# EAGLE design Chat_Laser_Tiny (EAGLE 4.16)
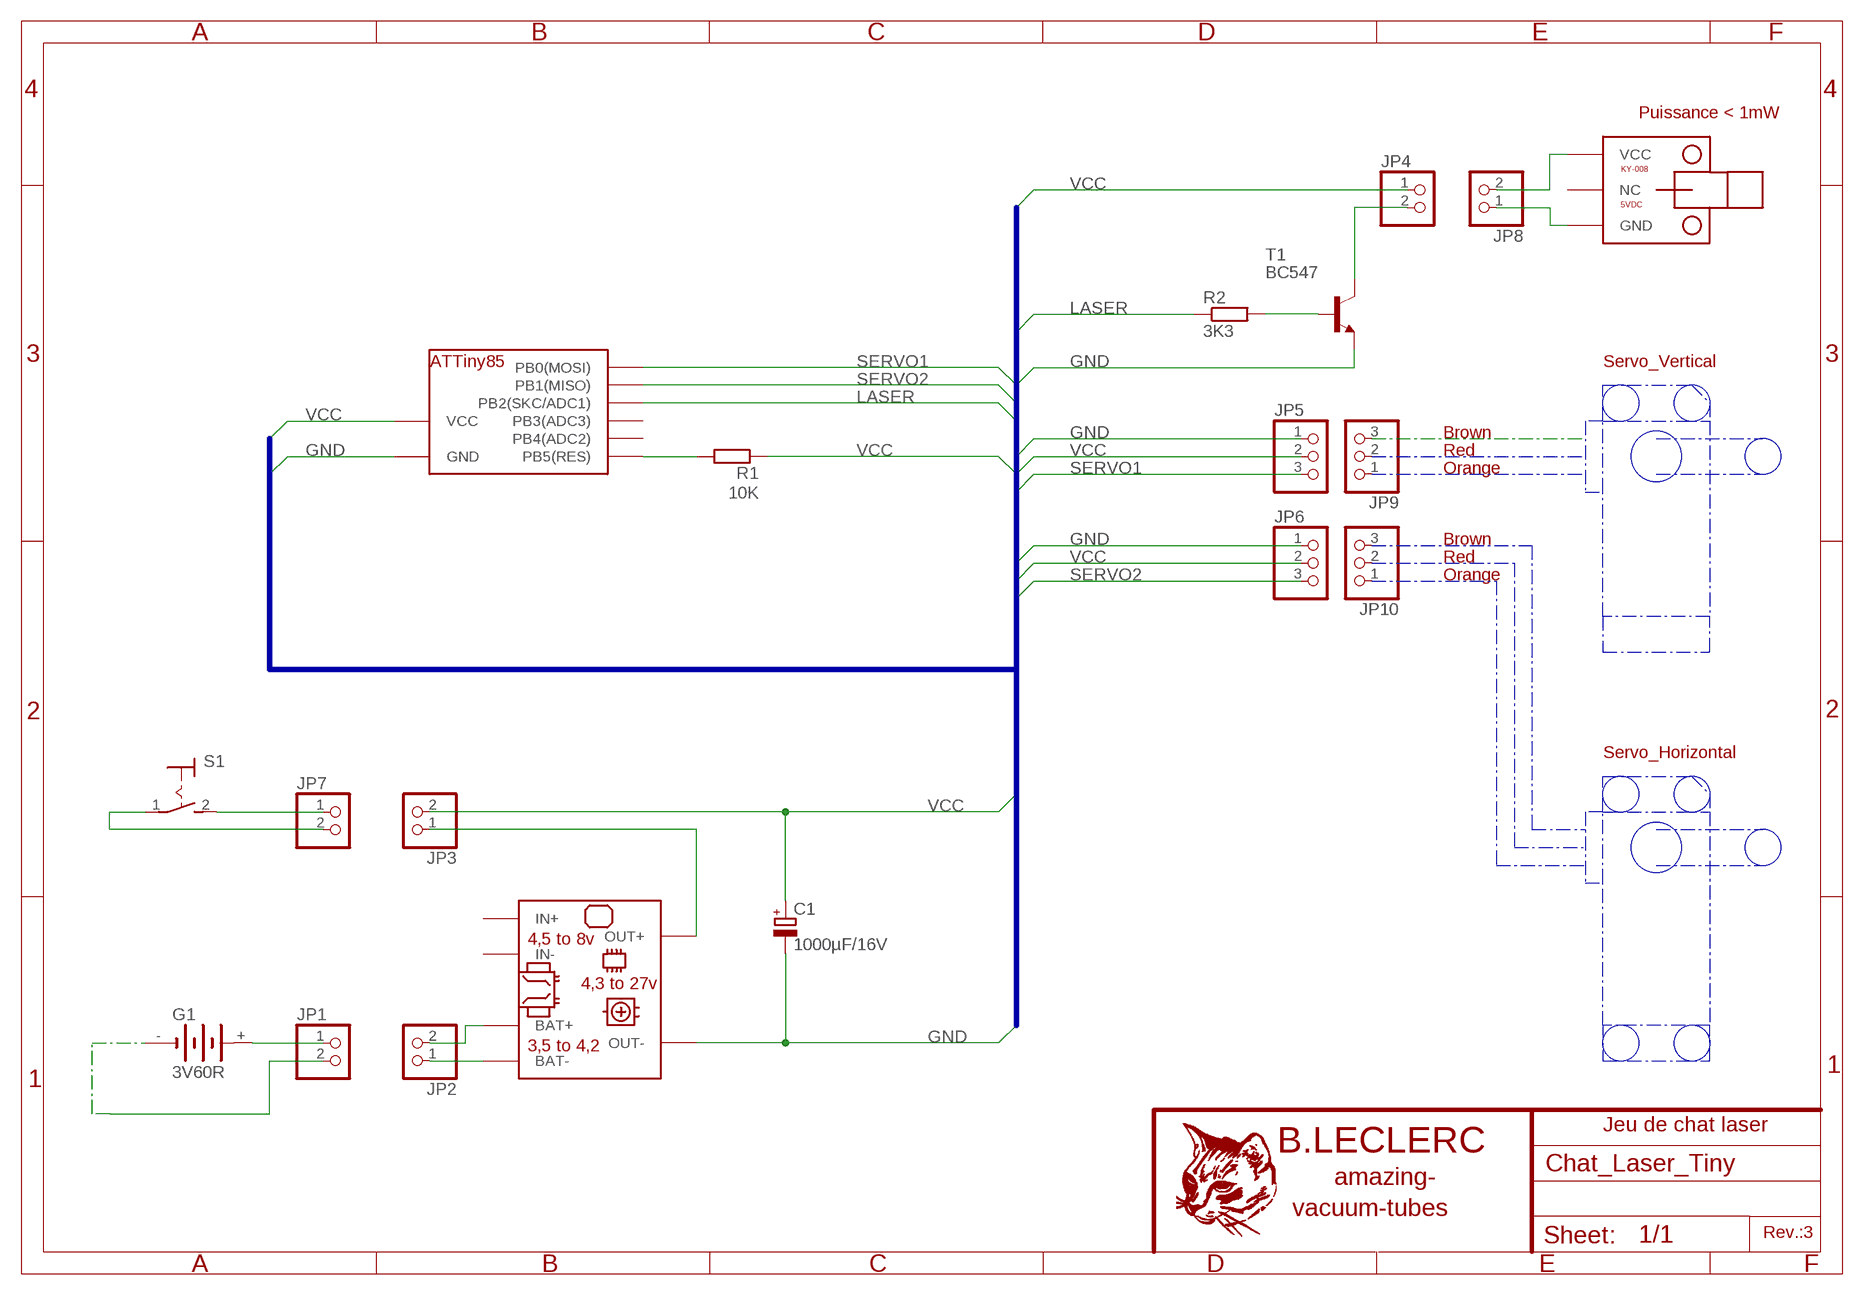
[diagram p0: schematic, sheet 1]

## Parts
C1  1000µF/16V  CPOL-EUE5-8.5  [E5-8,5]
G1  3V60R  [3V60R]
JP1  PINHD-1X2  [1X02]
JP2  PINHD-1X2  [1X02]
JP3  PINHD-1X2  [1X02]
JP4  PINHD-1X2  [1X02]
JP5  PINHD-1X3  [1X03]
JP6  PINHD-1X3  [1X03]
JP7  PINHD-1X2  [1X02]
JP8  PINHD-1X2  [1X02]
JP9  PINHD-1X3  [1X03]
JP10  PINHD-1X3  [1X03]
R1  10K  R-EU_M1206  [M1206]
R2  3K3  R-EU_M1206  [M1206]
S1  MS243  [MS243]
T1  BC547  [TO92]
U$2  LITHIUM_BAT_BOOST  [LITHIUM_BAT_BOOST]
U$3  KY-008_LASER  [KY-008_LASER]
U$4  ATTINY85  [DIL08]

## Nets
GND: C1.- JP5.1 JP6.1 T1.1(E) U$2.OUT- U$4.4(GND)
LASER: R2.1 U$4.7(PB2(SKC/ADC1))
N$1: R1.2 U$4.1(PB5(RES))
N$2: JP4.2 T1.3(C)
N$3: R2.2 T1.2(B)
N$6: G1.+ JP1.1
N$7: G1.- JP1.2
N$8: JP2.1 U$2.BAT-
N$9: JP2.2 U$2.BAT+
N$10: JP3.1 U$2.OUT+
N$11: JP7.2 S1.1(P)
N$12: JP7.1 S1.2(S)
N$13: JP8.2 U$3.VCC
N$14: JP8.1 U$3.GND
N$15: JP9.3
SERVO1: JP5.3 U$4.5(PB0(MOSI))
SERVO2: JP6.3 U$4.6(PB1(MISO))
VCC: C1.+ JP3.2 JP4.1 JP5.2 JP6.2 R1.1 U$4.8(VCC)
Unconnected: G1.+@1(+) JP9.1 JP9.2 JP10.1 JP10.2 JP10.3 U$3.NC U$4.2(PB3(ADC3)) U$4.3(PB4(ADC2))

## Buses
B$1
B$2
B$3
B$4
B$5
B$6
B$7
B$8
B$9
B$10
B$11
B$12

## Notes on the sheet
- Puissance < 1mW
- Servo_Vertical
- Brown
- Red
- Orange
- Brown
- Red
- Orange
- Servo_Horizontal
- Jeu de chat laser
- Rev.:3

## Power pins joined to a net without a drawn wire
IN+: U$2.IN+
IN-: U$2.IN-

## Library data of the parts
C1 = rcl:CPOL-EU: POLARIZED CAPACITOR, European symbol
G1 = battery:3V60R: NC ACCU Varta
JP1-JP4 JP7 JP8 = pinhead:PINHD-1X2: PIN HEADER
JP5 JP6 JP9 JP10 = pinhead:PINHD-1X3: PIN HEADER
R1 R2 = rcl:R-EU_: RESISTOR, European symbol
S1 = switch:MS243: TOGGLE SWITCH
T1 = transistor:BC547: NPN TRANSISTOR
U$2 = Arduino:LITHIUM_BAT_BOOST
U$3 = Arduino:KY-008_LASER
U$4 = atmel:ATTINY85

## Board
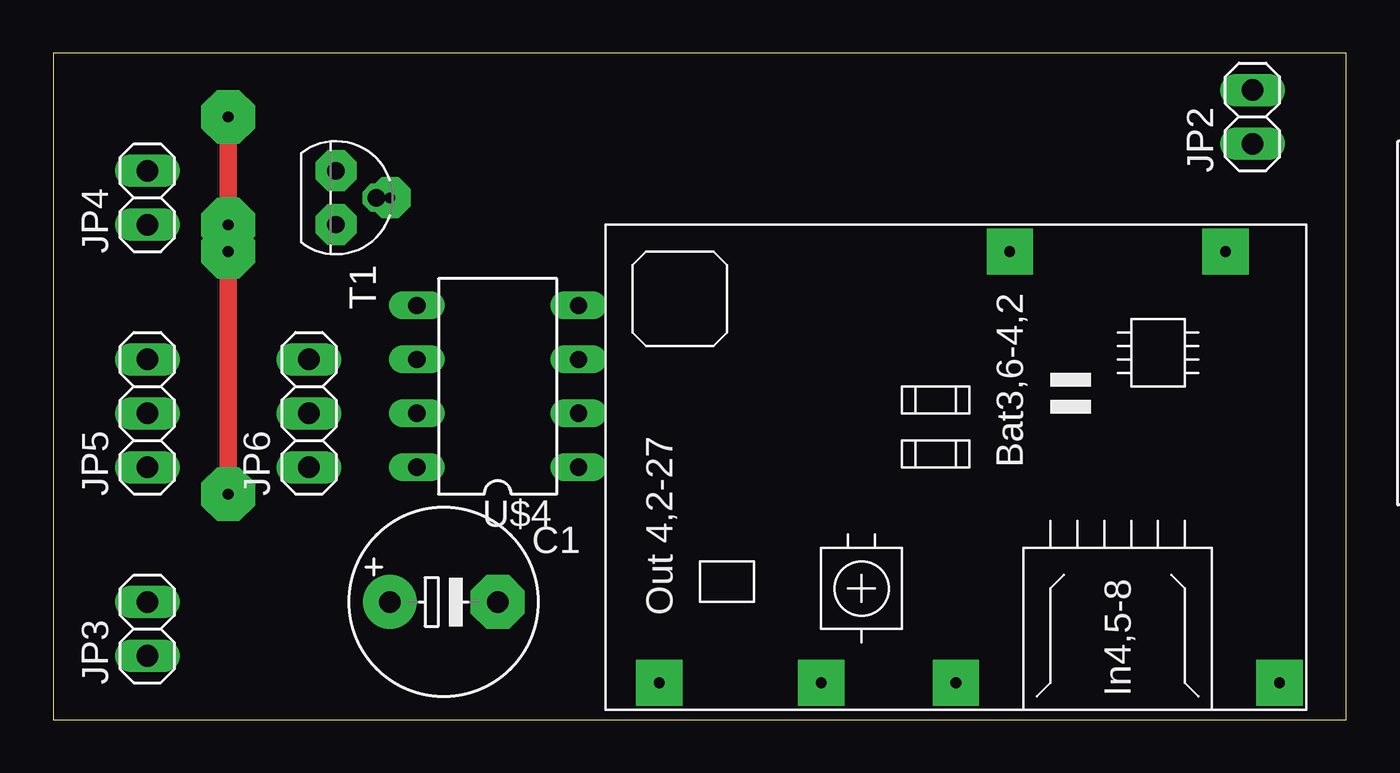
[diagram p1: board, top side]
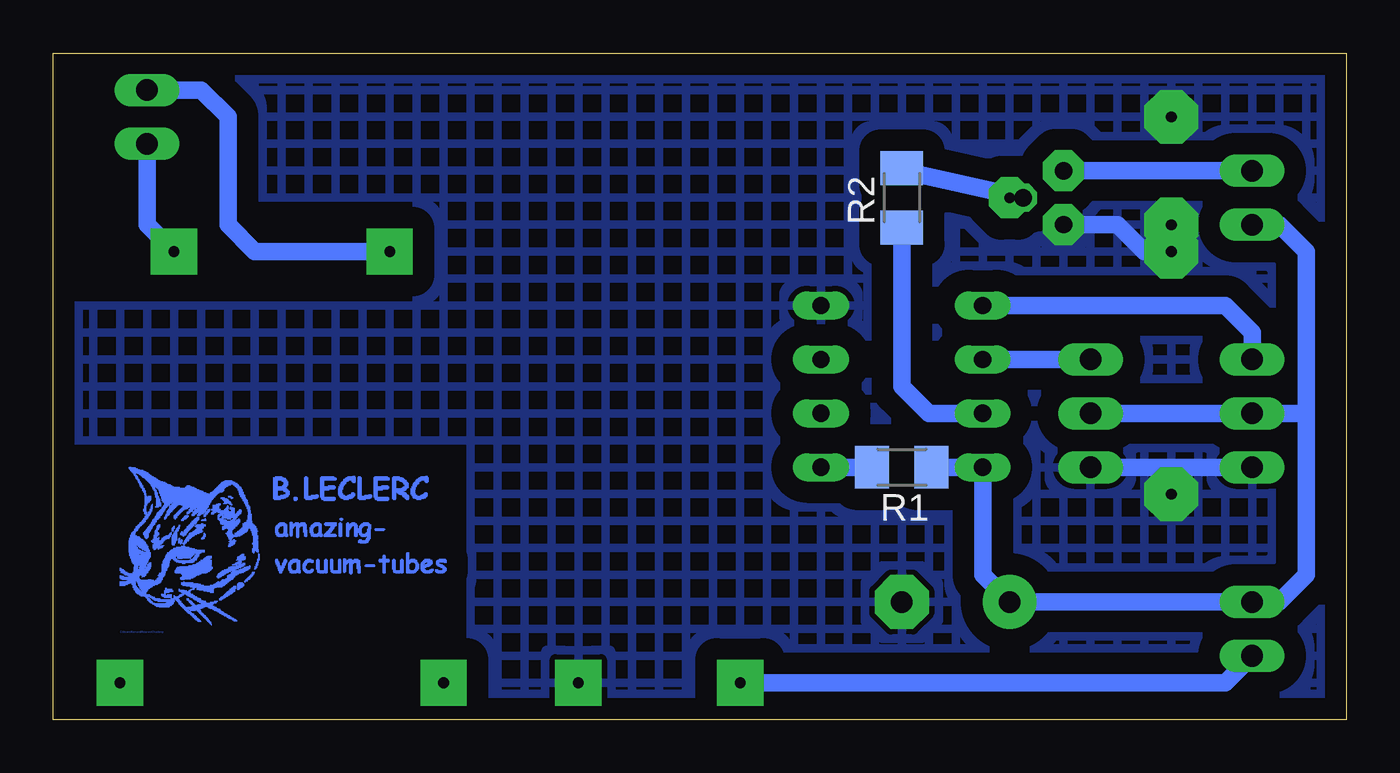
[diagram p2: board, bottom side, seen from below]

Size 60.94 x 31.42 mm. Coordinates in mm from the lower left corner, seen from the top.
Outline: 0,0 60.94,0 60.94,31.42 0,31.42 0,0
Copper layers (1*16): Top 0.035mm / dielectric 1.5mm / Bottom 0.035mm
Design rules "default": minimum track width 10mil, minimum drill 24mil, track to track 8mil, track to pad 8mil, pad to pad 8mil, via to via 8mil, smd to smd 8mil, copper to edge 40mil, drill to drill 8mil, minimum pad ring 10mil, minimum via ring 8mil, stop-mask expansion 4mil, vias tented up to drill 0mil, thermal gap 10mil

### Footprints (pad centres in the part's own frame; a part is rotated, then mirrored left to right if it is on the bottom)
E5-8,5 = drill 1.016 pad 2.54 round: + -2.54,0 | drill 1.016 pad 2.54 octagon: - 2.54,0
3V60R = drill 1.321 pad 3.15 octagon: + -10.16,-5.08; +@1 -10.16,5.08; - 9.271,0
1X02 = drill 1.016 long: 1 -1.27,0; 2 1.27,0
1X03 = drill 1.016 long: 1 -2.54,0; 2 0,0; 3 2.54,0
M1206 = smd 1.6 x 2: 1 -1.4,0; 2 1.4,0
MS243 = drill 1.803 pad 2 long: 1 0,-1.346; 2 0,1.346
TO92 = drill 0.813 octagon: 1 1.27,0; 2 0,1.905; 3 -1.27,0
LITHIUM_BAT_BOOST = drill 0.5 pad 2.184 square: BAT+ 20.32,12.7; BAT- 20.32,2.54; IN+ 0,15.24; IN- 0,0; OUT+ 0,29.21; OUT- 0,21.59
KY-008_LASER = drill 0.5 offset: GND 0,-2.54; NC 0,0; VCC 0,2.54
DIL08 = drill 0.813 long: 1 -3.81,-3.81; 2 -1.27,-3.81; 3 1.27,-3.81; 4 3.81,-3.81; 5 3.81,3.81; 6 1.27,3.81; 7 -1.27,3.81; 8 -3.81,3.81

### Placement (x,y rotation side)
C1  18.41,5.55 0 top
G1  not placed on the board
JP1  not placed on the board
JP2  56.51,28.41 90 top
JP3  4.44,4.28 90 top
JP4  4.44,24.6 90 top
JP5  4.44,14.44 90 top
JP6  12.06,14.44 90 top
JP7  not placed on the board
JP8  not placed on the board
JP9  not placed on the board
JP10  not placed on the board
R1  20.95,11.9 180 bottom
R2  20.95,24.6 90 bottom
S1  not placed on the board
T1  13.33,24.6 270 top
U$2  57.78,1.74 90 top
U$3  not placed on the board
U$4  20.95,15.71 90 top
U$5  [CHAT]  57.78,4.28 0 bottom

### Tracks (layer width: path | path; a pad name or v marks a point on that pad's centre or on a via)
GND  (via drill 0.5 pad 1.27, 0.5 pad 1.93, 0.5 pad 2.54)
  Top 0.813: v8.25,10.63 v8.25,23.33 v8.25,28.41
  Bottom 0.813: JP5.1 8.25,11.9 | 8.25,11.9 JP6.1 | 8.25,11.9 v8.25,10.63 | T1.1 10.79,23.33 9.52,22.06 v8.25,22.06
  other vias: 13.33,23.33 24.76,19.52 4.44,11.9 12.06,11.9
  pour Bottom (isolate 1.016, hatched): 0.63,30.95 52.7,30.95 52.7,24.6 43.81,24.6 43.81,19.52 60.32,19.52 60.32,13.17 41.27,13.17 41.27,0.47 0.63,0.47
LASER
  Bottom 0.813: U$4.7 19.68,14.44 20.95,15.71 R2.1 20.95,23.33
N$1
  Bottom 0.813: R1.2 U$4.1
N$2
  Bottom 0.813: JP4.2 T1.3
N$3
  Bottom 0.813: R2.2 20.95,25.87 T1.2
N$4  (via drill 0.5 pad 1.27)
  other vias: 4.44,25.87
N$5  (via drill 0.5 pad 1.93)
  other vias: 13.33,25.87
N$6  (1 unrouted)
N$7  (1 unrouted)
N$8
  Bottom 0.813: JP2.1 56.51,23.33 U$2.BAT-
N$9
  Bottom 0.813: JP2.2 53.97,29.68 52.7,28.41 52.7,23.33 51.43,22.06 U$2.BAT+
N$10
  Bottom 0.813: U$2.OUT+ 5.71,1.74 JP3.1
N$11  (1 unrouted)
N$12  (1 unrouted)
N$13  (1 unrouted)
N$14  (1 unrouted)
N$16  (via drill 0.5 pad 1.93)
  other vias: 15.87,24.6
N$17  (via drill 0.5 pad 1.27)
  other vias: 56.51,29.68
N$18  (via drill 0.5 pad 1.27)
  other vias: 12.06,14.44
N$19  (via drill 0.5 pad 1.27)
  other vias: 17.14,19.52
N$20  (via drill 0.5 pad 1.27)
  other vias: 24.76,11.9
N$21  (via drill 0.5 pad 1.27)
  other vias: 24.76,14.44
N$22  (via drill 0.5 pad 1.27)
  other vias: 24.76,16.98
N$23  (via drill 0.5 pad 1.27)
  other vias: 56.51,27.14
N$24  (via drill 0.5 pad 1.27)
  other vias: 4.44,3.01
N$25  (via drill 0.5 pad 1.27)
  other vias: 4.44,5.55
N$26  (via drill 0.5 pad 1.27)
  other vias: 4.44,23.33
N$27  (via drill 0.5 pad 1.27)
  other vias: 4.44,16.98
N$28  (via drill 0.5 pad 1.27)
  other vias: 4.44,14.44
N$30  (via drill 0.5 pad 1.27)
  other vias: 12.06,16.98
N$31  (via drill 0.5 pad 1.27)
  other vias: 17.14,16.98
N$32  (via drill 0.5 pad 1.27)
  other vias: 17.14,14.44
N$33  (via drill 0.5 pad 1.27)
  other vias: 17.14,11.9
SERVO1
  Bottom 0.813: JP5.3 4.44,18.25 5.71,19.52 U$4.5
SERVO2
  Bottom 0.813: JP6.3 U$4.6
VCC
  Bottom 0.813: JP6.2 JP5.2 1.9,14.44 | 1.9,14.44 1.9,6.82 3.17,5.55 JP3.2 C1.+ 17.14,6.82 U$4.8 R1.1 | JP4.1 3.17,23.33 1.9,22.06 1.9,14.44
